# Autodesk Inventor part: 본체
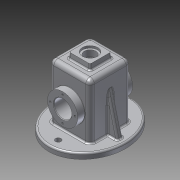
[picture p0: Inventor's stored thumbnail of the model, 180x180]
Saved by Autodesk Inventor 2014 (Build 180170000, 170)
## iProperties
Created: 2017-07
Part Number: 본체
Material: 알루미늄 6061
Document SubType Name: Modeling
Designer: user
Density: 2.71 g/cm^3
Appearance: 알루미늄 - 평지
Mass: 892.712 g
Surface Area: 987.354 cm^2
Volume: 329.414 cm^3
Author: user
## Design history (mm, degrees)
sketch "스케치1" dims "d6" = 65, "d7" = 75
  geometry: C1 r 5 at (-58, 0); C2 r 5 at (58, 0); 2 further points; 1 other entity
  constraints: 2 centre point, 1 coincident, 2 other
  dimensions: "d2" = 10 diameter of C1; "d3" = 10 diameter of C2; "d4" = 116 distance of C2.centre C1.centre; "d8" = 58 distance of point (0, 0) C1.centre; "d9" = 58 distance of point (0, 0) C2.centre
extrude "돌출1" new body sketch "스케치1" distance "d10" = 10; taper "d11" = 0 deg
node "작업 평면1"
sketch "스케치2"
  geometry: L1 (37, 37)-(-37, 37); L2 (-37, 37)-(-37, -37); L3 (-37, -37)-(37, -37); L4 (37, -37)-(37, 37); L5 (37, 37)-(-37, -37); L6 (-37, 37)-(37, -37); 1 further point
  constraints: 12 end point, 2 midpoint, 2 parallel, 1 horizontal, 1 perpendicular
  dimensions: "d13" = 74 distance of L3.end L2.end; "d14" = 74 distance of L2.end L1.end
extrude "돌출2" join sketch "스케치2" stored distance "d15" = 10; taper "d16" = 0 deg
node "작업 평면2"
sketch "스케치3"
  geometry: L1 (-20, -20)-(20, -20); L2 (20, -20)-(20, 20); L3 (20, 20)-(-20, 20); L4 (-20, 20)-(-20, -20); L5 (-20, -20)-(20, 20); L6 (20, -20)-(-20, 20); 1 further point
  constraints: 12 end point, 2 midpoint, 2 parallel, 1 horizontal, 1 perpendicular
  dimensions: "d18" = 40 distance of L3.end L2.end; "d19" = 40 distance of L2.end L1.end
extrude "돌출3" join sketch "스케치3" stored distance "d20" = 10; taper "d21" = 0 deg
sketch "스케치4"
  geometry: L1 (-37, 110)-(-37, 10) reference; L2 (65, 10)-(-65, 10) reference; L3 (37, 110)-(37, 10) reference; L4 (-37, 82.194)-(-55, 10); L5 (55, 10)-(37, 82.194); L6 (-65, 10)-(-65, 0); L7 (65, 10)-(65, 0); L8 (-55, 10)-(-37, 10); L9 (-37, 82.194)-(-37, 10); L10 (37, 10)-(37, 82.194); L11 (37, 10)-(55, 10); 1 further point
  constraints: 16 end point, 4 point on line, 2 collinear, 2 parallel, 2 perpendicular
  dimensions: "d22" = 14 deg angle of L6 L4; "d23" = 14 deg angle of L7 L5; "d24" = 10 distance of L2.end L4.end; "d25" = 10 distance of L2.start L5.start; "d26" = 10 distance from line of L7.end L2; "d27" = 10 distance from line of L6.end L2
extrude "돌출4" join sketch "스케치4" stored distance "d28" = 10; taper "d29" = 0 deg
feature "면 기울기1" dims angle "d30" = 5 deg
feature "면 기울기2" dims angle "d31" = 5 deg
feature "면 기울기3" dims angle "d32" = 5 deg
feature "면 기울기4" dims angle "d33" = 5 deg
sketch "스케치5"
  geometry: L1 (-37, 37)-(-37, -37) reference; L2 (-5, 37)-(-37, 37) reference; L3 (-5, 37)-(5, 37) reference; L4 (37, 37)-(5, 37) reference; L5 (37, -37)-(37, 37) reference; L6 (5, -37)-(37, -37) reference; L7 (-37, -37)-(-5, -37) reference; L8 (5, -37)-(-5, -37) reference; L9 (-32, -32)-(32, -32); L10 (32, -32)-(32, 32); L11 (32, 32)-(-32, 32); L12 (-32, 32)-(-32, -32); L13 (-32, -32)-(32, 32); L14 (32, -32)-(-32, 32); 1 further point; 1 other entity
  constraints: 12 end point, 2 midpoint, 2 parallel, 1 horizontal, 1 perpendicular, 1 other
  dimensions: "d34" = 64 distance of L11.end L10.end; "d35" = 64 distance of L10.end L9.end
extrude "돌출5" cut sketch "스케치5" distance "d36" = 105; taper "d37" = 0 deg
sketch "스케치6"
  geometry: 1 further point
hole "구멍1" sketch "스케치6" at (0, 0) diameter "d38" = 21; stored, may be unused: countersink angle "d42" = 90 deg, drill point angle "d44" = 118 deg; dims "d39" = 6, "d40" = 28, "d41" = 4, "d43" = 8
sketch "스케치7"
  geometry: L1 (-50, 55)-(50, 55); L2 (-50, 71)-(-50, 82.5); L3 (-32, 0)-(-32, 105) reference; L4 (32, 0)-(32, 105) reference; L5 (-50, 82.5)-(-32, 82.5); L6 (-32, 82.5)-(-25, 75.5); L7 (-25, 75.5)-(-25, 71); L8 (-25, 71)-(-50, 71); L9 (-37, 110)-(-37, 10) reference; L10 (37, 110)-(37, 10) reference; L11 (0, 55)-(0, 97.731); L12 (50, 71)-(50, 82.5); L13 (50, 82.5)-(32, 82.5); L14 (32, 82.5)-(25, 75.5); L15 (25, 75.5)-(25, 71); L16 (25, 71)-(50, 71); L17 (-50, 55)-(50, 55); L18 (50, 55)-(50, 71); L19 (50, 71)-(-50, 71); L20 (-50, 71)-(-50, 55); 1 further point
  constraints: 32 end point, 5 perpendicular, 5 symmetric about line, 3 parallel, 2 horizontal, 1 midpoint, 1 point on line, 1 vertical alignment
  dimensions: "d45" = 55 distance from line of point (0, 0) L1; "d46" = 100 distance of L1.start L1.end; "d47" = 7 horizontal distance of L5.end L6.end; "d48" = 55 diameter of L5 L1; "d49" = 32 diameter of L8 L1; "d50" = 13 distance between parallel lines of L9 L2; "d51" = 135 deg angle of L3 L6
revolve "회전1" stored, may be unused: angle "d52" = 90 deg
revolve "회전2" stored, may be unused: angle "d53" = 90 deg
sketch "스케치8" dims "d54" = 45
  geometry: L1 (0, 0)-(-22.5, 0); C1 r 27.5 at (0, 0) reference; 1 further point
  constraints: 2 end point, 1 coincident, 1 horizontal, 1 horizontal alignment, 2 other
hole "구멍2" sketch "스케치8" at (-22.5, 0) diameter "d55" = 3.242; stored, may be unused: countersink angle "d59" = 90 deg, drill point angle "d61" = 118 deg; dims "d56" = 8, "d57" = 28, "d58" = 4, "d60" = 10
fillet "모깎기1" dims "d65" = 3, "d66" = 8
fillet "모깎기2" dims "d67" = 8, "d68" = 3
fillet "모깎기3" dims "d69" = 3
fillet "모깎기4" dims "d70" = 3
chamfer "모따기1" distance "d71" = 1; stored, may be unused: second distance "d72" = 2, angle "d73" = 45 deg
fillet "모깎기5" dims "d74" = 0.5
fillet "모깎기6" dims "d75" = 3
node "작업 평면4"
fillet "모깎기7" dims "d81" = 3
node "작업 평면5"
sketch "스케치10"
  geometry: L1 (18, 45.137)-(18, 12.863) reference; L2 (-89, -8)-(0, -8) reference; 2 further points
  constraints: 1 other
  dimensions: "d83" = 30 distance from line of L1 point (-12, 29); "d84" = 37 distance from line of L2 point (-12, 29)
feature "엠보싱2" sketch "스케치10" dims "d2" = 10, "d18" = 40, "d19" = 40, "d85" = 0.5, "d86" = 0
node "솔리드1"
pattern_circular "원형 패턴1" dims angle "d63" = 360 deg
mirror "대칭1"
other parameters: "d82" = 76.75
